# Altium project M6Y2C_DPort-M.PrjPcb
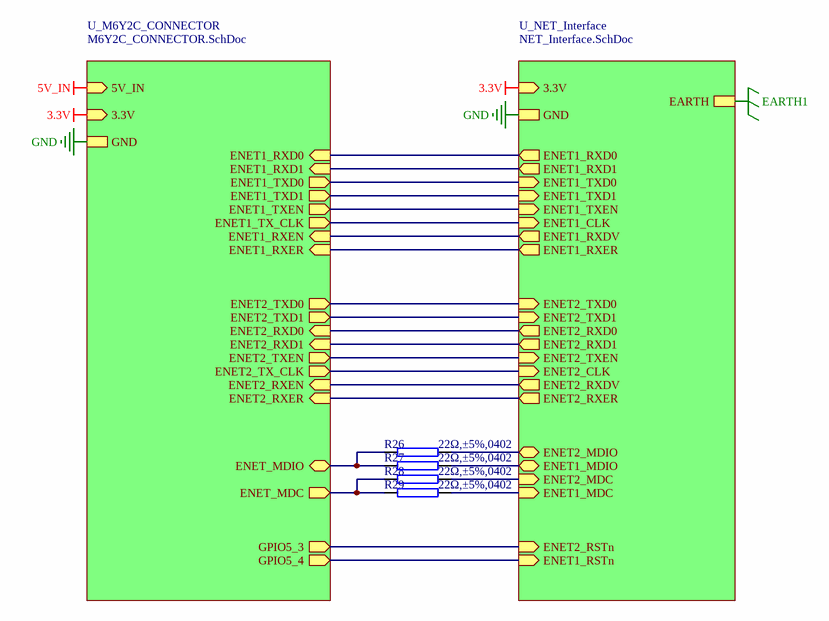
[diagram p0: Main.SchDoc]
3 sheets, 45 parts. Net scope: hierarchical (ports join the sheet entries above them; power ports are global).
Sheets:
  Main.SchDoc
    U_M6Y2C_CONNECTOR = M6Y2C_CONNECTOR.SchDoc
    U_NET_Interface = NET_Interface.SchDoc

## Sheet Main.SchDoc
size A4; CheckedBy: 工控机; Author: 工控机; SheetNumber: 01; PageSetup: Record=PageOptions¦CenterHorizontal=True¦CenterVertical=True¦PrintScale=1.00¦XCorrection=1.00¦YCorrection=1.00¦PrintKind=0¦BorderSize=5000000¦LeftOffset=0¦BottomOffset=0¦Orientation=2¦PaperLength=1000¦PaperWidth=1000¦Scale=100¦PaperSource=7¦PrintQuality=600¦MediaType=1¦DitherType=10¦PaperKind=A4¦PrintScaleMode=1; DesignDate: 2023/12/21; CheckDate: 2023/12/21; SheetName: Main; SheetVersion: Rev,A; SheetDescription: M6Y2C_DPort-M; ProductName: 集成式RJ45插座; ProductModel: DPort-M

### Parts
R26  22Ω,±5%,0402  [0402R]
R27  22Ω,±5%,0402  [0402R]
R28  22Ω,±5%,0402  [0402R]
R29  22Ω,±5%,0402  [0402R]

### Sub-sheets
U_M6Y2C_CONNECTOR = M6Y2C_CONNECTOR.SchDoc: ENET2_RXD1 (in), ENET2_RXD0 (in), ENET2_RXEN (in), ENET2_RXER (in), ENET_MDC (out), ENET2_TXD1 (out), ENET2_TXD0 (out), ENET2_TXEN (out), ENET2_TX_CLK (out), ENET_MDIO (bidir), ENET1_RXD1 (in), ENET1_RXD0 (in), ENET1_TXD1 (out), ENET1_TXD0 (out), ENET1_RXEN (in), ENET1_RXER (in), ENET1_TXEN (out), ENET1_TX_CLK (out), GND, 5V_IN (in), 3.3V (in), GPIO5_3 (out), GPIO5_4 (out)
U_NET_Interface = NET_Interface.SchDoc: GND, EARTH, ENET1_MDC (in), ENET1_RXDV (out), ENET1_TXEN (in), ENET1_MDIO (bidir), ENET1_RSTn (in), ENET1_TXD0 (in), ENET1_TXD1 (in), ENET1_RXD0 (out), ENET1_RXD1 (out), ENET1_CLK (in), ENET1_RXER (out), ENET2_MDC (in), ENET2_RXDV (out), ENET2_TXEN (in), ENET2_MDIO (bidir), ENET2_RSTn (in), ENET2_TXD0 (in), ENET2_TXD1 (in), ENET2_RXD0 (out), ENET2_RXD1 (out), ENET2_CLK (in), ENET2_RXER (out), 3.3V (in)

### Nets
3.3V: sheet U_M6Y2C_CONNECTOR/3.3V, sheet U_NET_Interface/3.3V
GND: sheet U_M6Y2C_CONNECTOR/GND, sheet U_NET_Interface/GND
ENET1_CLK: sheet U_M6Y2C_CONNECTOR/ENET1_TX_CLK, sheet U_NET_Interface/ENET1_CLK
ENET1_MDC: R29.2 ; sheet U_NET_Interface/ENET1_MDC
ENET1_MDIO: R27.2 ; sheet U_NET_Interface/ENET1_MDIO
ENET1_RSTn: sheet U_M6Y2C_CONNECTOR/GPIO5_4, sheet U_NET_Interface/ENET1_RSTn
ENET1_RXD0: sheet U_M6Y2C_CONNECTOR/ENET1_RXD0, sheet U_NET_Interface/ENET1_RXD0
ENET1_RXD1: sheet U_M6Y2C_CONNECTOR/ENET1_RXD1, sheet U_NET_Interface/ENET1_RXD1
ENET1_RXDV: sheet U_M6Y2C_CONNECTOR/ENET1_RXEN, sheet U_NET_Interface/ENET1_RXDV
ENET1_RXER: sheet U_M6Y2C_CONNECTOR/ENET1_RXER, sheet U_NET_Interface/ENET1_RXER
ENET1_TXD0: sheet U_M6Y2C_CONNECTOR/ENET1_TXD0, sheet U_NET_Interface/ENET1_TXD0
ENET1_TXD1: sheet U_M6Y2C_CONNECTOR/ENET1_TXD1, sheet U_NET_Interface/ENET1_TXD1
ENET1_TXEN: sheet U_M6Y2C_CONNECTOR/ENET1_TXEN, sheet U_NET_Interface/ENET1_TXEN
ENET2_CLK: sheet U_M6Y2C_CONNECTOR/ENET2_TX_CLK, sheet U_NET_Interface/ENET2_CLK
ENET2_MDC: R28.2 ; sheet U_NET_Interface/ENET2_MDC
ENET2_MDIO: R26.2 ; sheet U_NET_Interface/ENET2_MDIO
ENET2_RSTn: sheet U_M6Y2C_CONNECTOR/GPIO5_3, sheet U_NET_Interface/ENET2_RSTn
ENET2_RXD0: sheet U_M6Y2C_CONNECTOR/ENET2_RXD0, sheet U_NET_Interface/ENET2_RXD0
ENET2_RXD1: sheet U_M6Y2C_CONNECTOR/ENET2_RXD1, sheet U_NET_Interface/ENET2_RXD1
ENET2_RXDV: sheet U_M6Y2C_CONNECTOR/ENET2_RXEN, sheet U_NET_Interface/ENET2_RXDV
ENET2_RXER: sheet U_M6Y2C_CONNECTOR/ENET2_RXER, sheet U_NET_Interface/ENET2_RXER
ENET2_TXD0: sheet U_M6Y2C_CONNECTOR/ENET2_TXD0, sheet U_NET_Interface/ENET2_TXD0
ENET2_TXD1: sheet U_M6Y2C_CONNECTOR/ENET2_TXD1, sheet U_NET_Interface/ENET2_TXD1
ENET2_TXEN: sheet U_M6Y2C_CONNECTOR/ENET2_TXEN, sheet U_NET_Interface/ENET2_TXEN
ENET_MDC: R28.1 R29.1 ; sheet U_M6Y2C_CONNECTOR/ENET_MDC
ENET_MDIO: R26.1 R27.1 ; sheet U_M6Y2C_CONNECTOR/ENET_MDIO

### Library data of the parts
R26-R29 = 01.01.00014: RTT02220JTH,0402,RALEC,22Ω,±5%,1/16W,; 旧物料代码: 1.01.17.0023; 名称: 电阻; 封装: 0402; 贴片和直插: SMT; 环保状态: RoHS2.0+REACH; 器件优选方案: 通用物料; 生产单位: PCS

## Sheet M6Y2C_CONNECTOR.SchDoc
size A3; CheckedBy: 工控机; Author: 工控机; SheetNumber: 02; PageSetup: Record=PageOptions¦CenterHorizontal=True¦CenterVertical=True¦PrintScale=1.00¦XCorrection=1.00¦YCorrection=1.00¦PrintKind=0¦BorderSize=5000000¦LeftOffset=0¦BottomOffset=0¦Orientation=2¦PaperLength=1000¦PaperWidth=1000¦Scale=100¦PaperSource=7¦PrintQuality=600¦MediaType=1¦DitherType=10¦PaperKind=A4¦PrintScaleMode=1; DesignDate: 2023/12/21; CheckDate: 2023/12/21; SheetName: M6Y2C_CONNECTOER; SheetVersion: Rev.A; SheetDescription: M6Y2C_DPort-M; ProductName: 集成式RJ45插座; ProductModel: DPort-M
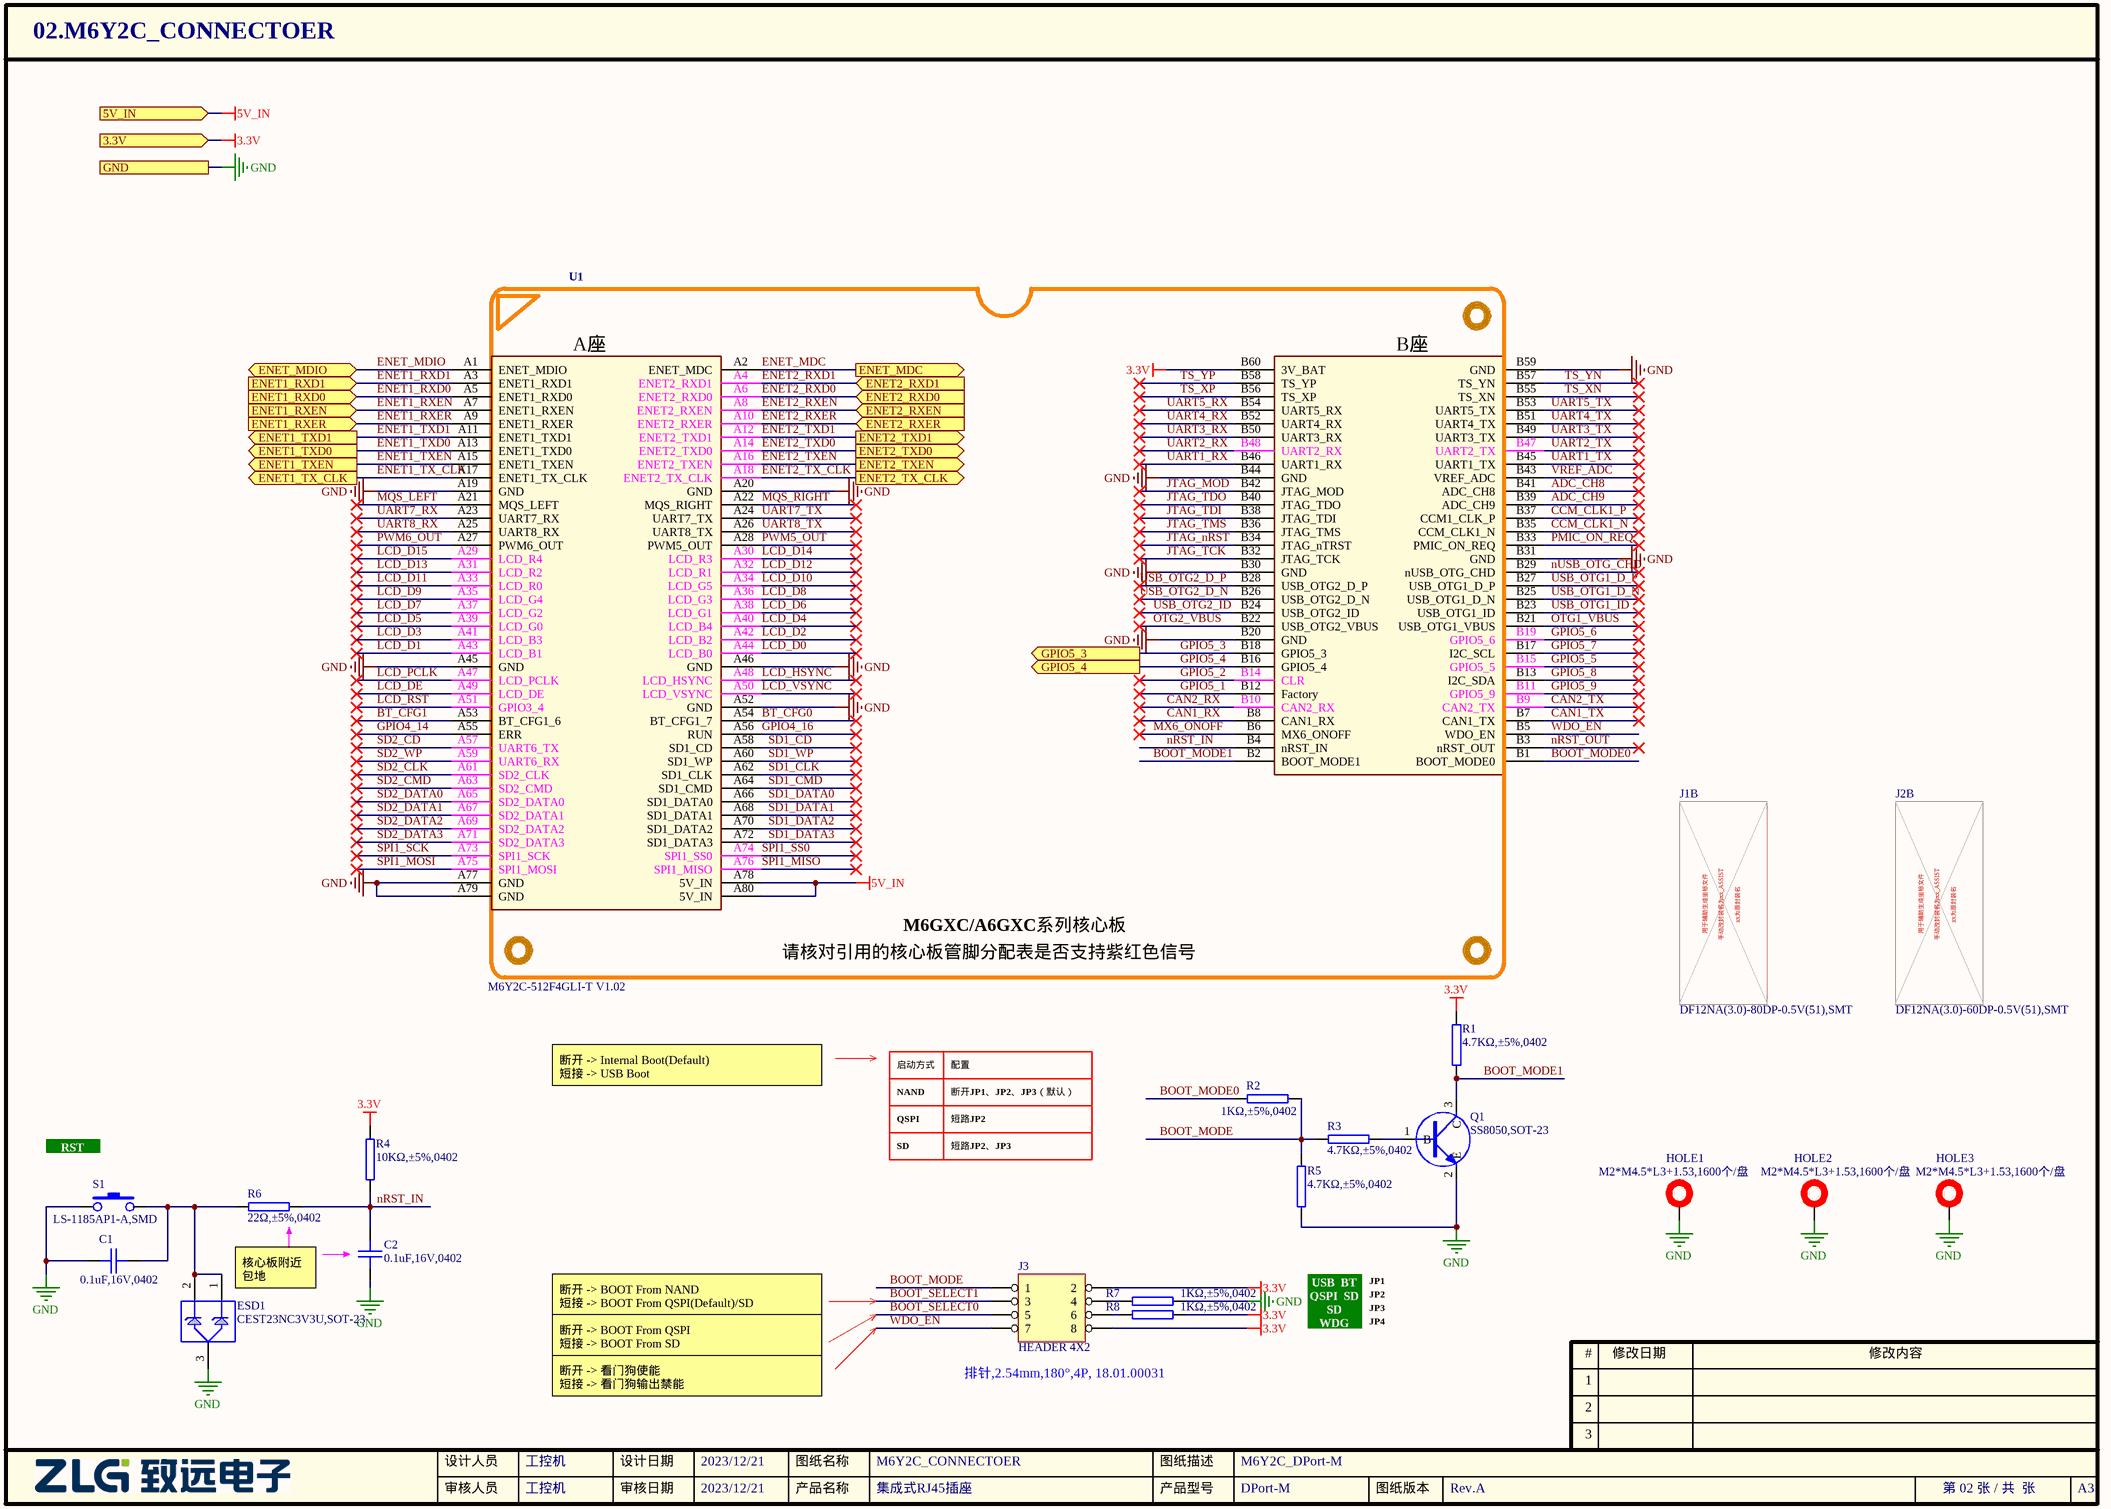
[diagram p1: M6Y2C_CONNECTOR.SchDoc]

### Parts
C1  0.1uF,16V,0402  [0402C]
C2  0.1uF,16V,0402  [0402C]
ESD1  CEST23NC3V3U,SOT-23  [SOT-23]
HOLE1  M2*M4.5*L3+1.53,1600个/盘  [Mou-Hole-300D450W310H-SMD]
HOLE2  M2*M4.5*L3+1.53,1600个/盘  [Mou-Hole-300D450W310H-SMD]
HOLE3  M2*M4.5*L3+1.53,1600个/盘  [Mou-Hole-300D450W310H-SMD]
J1  DF12NA(3.0)-80DP-0.5V(51),SMT  [SMTCON_DF12NA(3.0)-80DP-0.5V(51)]  (part B of 2)
J2  DF12NA(3.0)-60DP-0.5V(51),SMT  [SMTCON_DF12NA(3.0)-60DP-0.5V(51)]  (part B of 2)
J3  HEADER 4X2  [IDC-8-2.54]
Q1  SS8050,SOT-23  [SOT-23]
R1  4.7KΩ,±5%,0402  [0402R]
R2  1KΩ,±5%,0402  [0402R]
R3  4.7KΩ,±5%,0402  [0402R]
R4  10KΩ,±5%,0402  [0402R]
R5  4.7KΩ,±5%,0402  [0402R]
R6  22Ω,±5%,0402  [0402R]
R7  1KΩ,±5%,0402  [0402R]
R8  1KΩ,±5%,0402  [0402R]
S1  LS-1185AP1-A,SMD  [KEY-400X300X200P]
U1  M6Y2C-512F4GLI-T V1.02  [M6205/A6GXC]

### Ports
3.3V (in), 5V_IN (in), ENET1_RXD0 (in), ENET1_RXD1 (in), ENET1_RXEN (in), ENET1_RXER (in), ENET1_TX_CLK (out), ENET1_TXD0 (out), ENET1_TXD1 (out), ENET1_TXEN (out), ENET2_RXD0 (in), ENET2_RXD1 (in), ENET2_RXEN (in), ENET2_RXER (in), ENET2_TX_CLK (out), ENET2_TXD0 (out), ENET2_TXD1 (out), ENET2_TXEN (out), ENET_MDC (out), ENET_MDIO (bidir), GND, GPIO5_3 (out), GPIO5_4 (out)

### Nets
3.3V: J3.2 J3.8 R1.2 R4.2 R8.2 U1.B60(3V_BAT) ; port 3.3V
5V_IN: U1.A78(5V_IN) U1.A80(5V_IN) ; port 5V_IN
GND: C1.1 C2.2 ESD1.3 HOLE1.1 HOLE2.1 HOLE3.1 Q1.2(E) R5.1 R7.2 S1.1 U1.A19(GND) U1.A20(GND) U1.A45(GND) U1.A46(GND) U1.A52(GND) U1.A77(GND) U1.A79(GND) U1.B20(GND) U1.B30(GND) U1.B31(GND) U1.B44(GND) U1.B59(GND) ; port GND
ADC_CH8: U1.B41(ADC_CH8)
ADC_CH9: U1.B39(ADC_CH9)
BOOT_MODE: J3.1 R2.2 R3.1 R5.2
BOOT_MODE0: R2.1 U1.B1(BOOT_MODE0)
BOOT_MODE1: Q1.3(C) R1.1 U1.B2(BOOT_MODE1)
BOOT_SELECT0: J3.5
BOOT_SELECT1: J3.3
BT_CFG0: U1.A54(BT_CFG1_7)
BT_CFG1: U1.A53(BT_CFG1_6)
CAN1_RX: U1.B8(CAN1_RX)
CAN1_TX: U1.B7(CAN1_TX)
CAN2_RX: U1.B10(CAN2_RX)
CAN2_TX: U1.B9(CAN2_TX)
CCM_CLK1_N: U1.B35(CCM_CLK1_N)
CCM_CLK1_P: U1.B37(CCM1_CLK_P)
ENET1_RXD0: U1.A5(ENET1_RXD0) ; port ENET1_RXD0
ENET1_RXD1: U1.A3(ENET1_RXD1) ; port ENET1_RXD1
ENET1_RXEN: U1.A7(ENET1_RXEN) ; port ENET1_RXEN  [project net ENET1_RXDV]
ENET1_RXER: U1.A9(ENET1_RXER) ; port ENET1_RXER
ENET1_TX_CLK: U1.A17(ENET1_TX_CLK) ; port ENET1_TX_CLK  [project net ENET1_CLK]
ENET1_TXD0: U1.A13(ENET1_TXD0) ; port ENET1_TXD0
ENET1_TXD1: U1.A11(ENET1_TXD1) ; port ENET1_TXD1
ENET1_TXEN: U1.A15(ENET1_TXEN) ; port ENET1_TXEN
ENET2_RXD0: U1.A6(ENET2_RXD0) ; port ENET2_RXD0
ENET2_RXD1: U1.A4(ENET2_RXD1) ; port ENET2_RXD1
ENET2_RXEN: U1.A8(ENET2_RXEN) ; port ENET2_RXEN  [project net ENET2_RXDV]
ENET2_RXER: U1.A10(ENET2_RXER) ; port ENET2_RXER
ENET2_TX_CLK: U1.A18(ENET2_TX_CLK) ; port ENET2_TX_CLK  [project net ENET2_CLK]
ENET2_TXD0: U1.A14(ENET2_TXD0) ; port ENET2_TXD0
ENET2_TXD1: U1.A12(ENET2_TXD1) ; port ENET2_TXD1
ENET2_TXEN: U1.A16(ENET2_TXEN) ; port ENET2_TXEN
ENET_MDC: U1.A2(ENET_MDC) ; port ENET_MDC
ENET_MDIO: U1.A1(ENET_MDIO) ; port ENET_MDIO
GPIO4_14: U1.A55(ERR)
GPIO4_16: U1.A56(RUN)
GPIO5_1: U1.B12(Factory)
GPIO5_2: U1.B14(CLR)
GPIO5_3: U1.B18(GPIO5_3) ; port GPIO5_3  [project net ENET2_RSTn]
GPIO5_4: U1.B16(GPIO5_4) ; port GPIO5_4  [project net ENET1_RSTn]
GPIO5_5: U1.B15(GPIO5_5)
GPIO5_6: U1.B19(GPIO5_6)
GPIO5_7: U1.B17(I2C_SCL)
GPIO5_8: U1.B13(I2C_SDA)
GPIO5_9: U1.B11(GPIO5_9)
JTAG_MOD: U1.B42(JTAG_MOD)
JTAG_nRST: U1.B34(JTAG_nTRST)
JTAG_TCK: U1.B32(JTAG_TCK)
JTAG_TDI: U1.B38(JTAG_TDI)
JTAG_TDO: U1.B40(JTAG_TDO)
JTAG_TMS: U1.B36(JTAG_TMS)
LCD_D0: U1.A44(LCD_B0)
LCD_D1: U1.A43(LCD_B1)
LCD_D2: U1.A42(LCD_B2)
LCD_D3: U1.A41(LCD_B3)
LCD_D4: U1.A40(LCD_B4)
LCD_D5: U1.A39(LCD_G0)
LCD_D6: U1.A38(LCD_G1)
LCD_D7: U1.A37(LCD_G2)
LCD_D8: U1.A36(LCD_G3)
LCD_D9: U1.A35(LCD_G4)
LCD_D10: U1.A34(LCD_G5)
LCD_D11: U1.A33(LCD_R0)
LCD_D12: U1.A32(LCD_R1)
LCD_D13: U1.A31(LCD_R2)
LCD_D14: U1.A30(LCD_R3)
LCD_D15: U1.A29(LCD_R4)
LCD_DE: U1.A49(LCD_DE)
LCD_HSYNC: U1.A48(LCD_HSYNC)
LCD_PCLK: U1.A47(LCD_PCLK)
LCD_RST: U1.A51(GPIO3_4)
LCD_VSYNC: U1.A50(LCD_VSYNC)
MQS_LEFT: U1.A21(MQS_LEFT)
MQS_RIGHT: U1.A22(MQS_RIGHT)
MX6_ONOFF: U1.B6(MX6_ONOFF)
nRST_IN: C2.1 R4.1 R6.2 U1.B4(nRST_IN)
nRST_OUT: U1.B3(nRST_OUT)
nUSB_OTG_CHD: U1.B29(nUSB_OTG_CHD)
OTG1_VBUS: U1.B21(USB_OTG1_VBUS)
OTG2_VBUS: U1.B22(USB_OTG2_VBUS)
PMIC_ON_REQ: U1.B33(PMIC_ON_REQ)
PWM5_OUT: U1.A28(PWM5_OUT)
PWM6_OUT: U1.A27(PWM6_OUT)
SD1_CD: U1.A58(SD1_CD)
SD1_CLK: U1.A62(SD1_CLK)
SD1_CMD: U1.A64(SD1_CMD)
SD1_DATA0: U1.A66(SD1_DATA0)
SD1_DATA1: U1.A68(SD1_DATA1)
SD1_DATA2: U1.A70(SD1_DATA2)
SD1_DATA3: U1.A72(SD1_DATA3)
SD1_WP: U1.A60(SD1_WP)
SD2_CD: U1.A57(UART6_TX)
SD2_CLK: U1.A61(SD2_CLK)
SD2_CMD: U1.A63(SD2_CMD)
SD2_DATA0: U1.A65(SD2_DATA0)
SD2_DATA1: U1.A67(SD2_DATA1)
SD2_DATA2: U1.A69(SD2_DATA2)
SD2_DATA3: U1.A71(SD2_DATA3)
SD2_WP: U1.A59(UART6_RX)
SPI1_MISO: U1.A76(SPI1_MISO)
SPI1_MOSI: U1.A75(SPI1_MOSI)
SPI1_SCK: U1.A73(SPI1_SCK)
SPI1_SS0: U1.A74(SPI1_SS0)
TS_XN: U1.B55(TS_XN)
TS_XP: U1.B56(TS_XP)
TS_YN: U1.B57(TS_YN)
TS_YP: U1.B58(TS_YP)
UART1_RX: U1.B46(UART1_RX)
UART1_TX: U1.B45(UART1_TX)
UART2_RX: U1.B48(UART2_RX)
UART2_TX: U1.B47(UART2_TX)
UART3_RX: U1.B50(UART3_RX)
UART3_TX: U1.B49(UART3_TX)
UART4_RX: U1.B52(UART4_RX)
UART4_TX: U1.B51(UART4_TX)
UART5_RX: U1.B54(UART5_RX)
UART5_TX: U1.B53(UART5_TX)
UART7_RX: U1.A23(UART7_RX)
UART7_TX: U1.A24(UART7_TX)
UART8_RX: U1.A25(UART8_RX)
UART8_TX: U1.A26(UART8_TX)
USB_OTG1_D_N: U1.B25(USB_OTG1_D_N)
USB_OTG1_D_P: U1.B27(USB_OTG1_D_P)
USB_OTG1_ID: U1.B23(USB_OTG1_ID)
USB_OTG2_D_N: U1.B26(USB_OTG2_D_N)
USB_OTG2_D_P: U1.B28(USB_OTG2_D_P)
USB_OTG2_ID: U1.B24(USB_OTG2_ID)
VREF_ADC: U1.B43(VREF_ADC)
WDO_EN: J3.7 U1.B5(WDO_EN)
NetC1_2: C1.2 ESD1.1 ESD1.2 R6.1 S1.2
NetJ3_4: J3.4 R7.1
NetJ3_6: J3.6 R8.1
NetQ1_1: Q1.1(B) R3.2

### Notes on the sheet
- 断开 -> Internal Boot(Default)
  短接 -> USB Boot
- 启动方式
- NAND
- QSPI
- 断开JP1、JP2、JP3（默认）
- 短路JP2
- 配置
- RST
- SD
- 短路JP2、JP3
- (near ESD1) 核心板附近 包地
- 断开 -> BOOT From NAND
  短接 -> BOOT From QSPI(Default)/SD
- USB_BT
- QSPI_SD
- WDG
- JP1
- JP2
- JP3
- JP4
- 断开 -> 看门狗使能
  短接 -> 看门狗输出禁能
- 断开 -> BOOT From QSPI
  短接 -> BOOT From SD
- 排针,2.54mm,180°,4P, 18.01.00031

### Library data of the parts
C1 C2 = 02.01.00513: CC0402KRX7R7BB104,0402,YAGEO,0.1uF,X7R,±10%,16V,; 名称: 电容; 封装: 0402; 贴片和直插: SMT; 环保状态: RoHS2.0; PCB备注: 211228yyj; 器件优选方案: 通用物料; 生产单位: PCS
ESD1 = 09.04.00444: CEST23NC3V3U,SOT-23,CREATEK; 名称: ESD静电保护器件; 贴片和直插: SMT; 环保状态: RoHS2.0; 器件优选方案: 通用物料; 生产单位: PCS; PCB备注: 220609lmd
HOLE1-HOLE3 = 27.41.00039: M2*M4.5*L3+1.53,1600个/盘,雄和远景; 名称: 螺柱; 贴片和直插: SMT; PCB备注: 160330lmd; 器件优选方案: 通用物料; 旧物料代码: 1.15.03.0047
J1 = 18.04.00097: DF12NA(3.0)-80DP-0.5V(51),SMT,HRS; 名称: 板对板连接器; 环保状态: RoHS2.0; PCB备注: 210805ZW; 器件优选方案: 通用物料; 生产单位: PCS
J2 = 18.04.00099: DF12NA(3.0)-60DP-0.5V(51),SMT,HRS; 名称: 板对板连接器; 环保状态: RoHS2.0; PCB备注: 210805ZW; 器件优选方案: 通用物料; 生产单位: PCS
Q1 = 05.01.00095: SS8050,SOT-23,JCET,NPN,; 旧物料代码: 1.04.09.0001; 名称: 双极结型晶体管(三极管); 贴片和直插: SMT; 环保状态: RoHS2.0+REACH; 器件优选方案: 通用物料; 生产单位: PCS
R1 R3 R5 = 01.01.00003: RTT02472JTH,0402,RALEC,4.7KΩ,±5%,1/16W,; 旧物料代码: 1.01.17.0019; 名称: 电阻; 封装: 0402; 贴片和直插: SMT; 环保状态: RoHS2.0+REACH; 器件优选方案: 通用物料; 生产单位: PCS
R2 = 01.01.00007: RTT02102JTH,0402,RALEC,1KΩ,±5%,1/16W,; 旧物料代码: 1.01.17.0022; 名称: 电阻; 封装: 0402; 贴片和直插: SMT; 环保状态: RoHS2.0+REACH; 器件优选方案: 通用物料; 生产单位: PCS
R4 = 01.01.00001: RTT02103JTH,0402,RALEC,10KΩ,±5%,1/16W; 旧物料代码: 1.01.17.0006; 名称: 电阻; 封装: 0402; 贴片和直插: SMT; 环保状态: RoHS2.0; 器件优选方案: 通用物料; 生产单位: PCS
R6 = 01.01.00014: as R26 on sheet Main
R7 R8 = 01.01.00007: RTT02102JTH,0402,RALEC,1KΩ,±5%,1/16W,; 旧物料代码: 1.01.17.0022; 名称: 电阻; 封装: 0402; 贴片和直插: SMT; 器件优选方案: 通用物料
S1 = 17.01.00009: LS-1185AP1-A,SMD,CKC,4*3*2mm,; 旧物料代码: 1.09.01.0017; 名称: 轻触开关; 封装: SMT; 环保状态: RoHS2.0; PCB备注: 161024 HCJ; 器件优选方案: 通用物料; 生产单位: PCS
U1 = 80.08.90523: 名称: 核心板; PCB备注: 221027hcj; 厂商: ZHIYUAN; 环保状态: RoHS2.0; 生产单位: PCS

## Sheet NET_Interface.SchDoc
size A4; CheckedBy: 工控机; Author: 工控机; SheetNumber: 2; SheetTotal: 2; PageSetup: Record=PageOptions¦CenterHorizontal=True¦CenterVertical=True¦PrintScale=1.00¦XCorrection=1.00¦YCorrection=1.00¦PrintKind=0¦BorderSize=5000000¦LeftOffset=0¦BottomOffset=0¦Orientation=2¦PaperLength=1000¦PaperWidth=1000¦Scale=100¦PaperSource=7¦PrintQuality=600¦MediaType=1¦DitherType=10¦PaperKind=A4¦PrintScaleMode=1; DesignDate: 2023/12/21; CheckDate: 2023/12/21; SheetName: NET_Interface; SheetVersion: Rev.A; SheetDescription: 集成PHY和网络变压器的双口RJ45; ProductName: RJ45插座; ProductModel: DPort-M
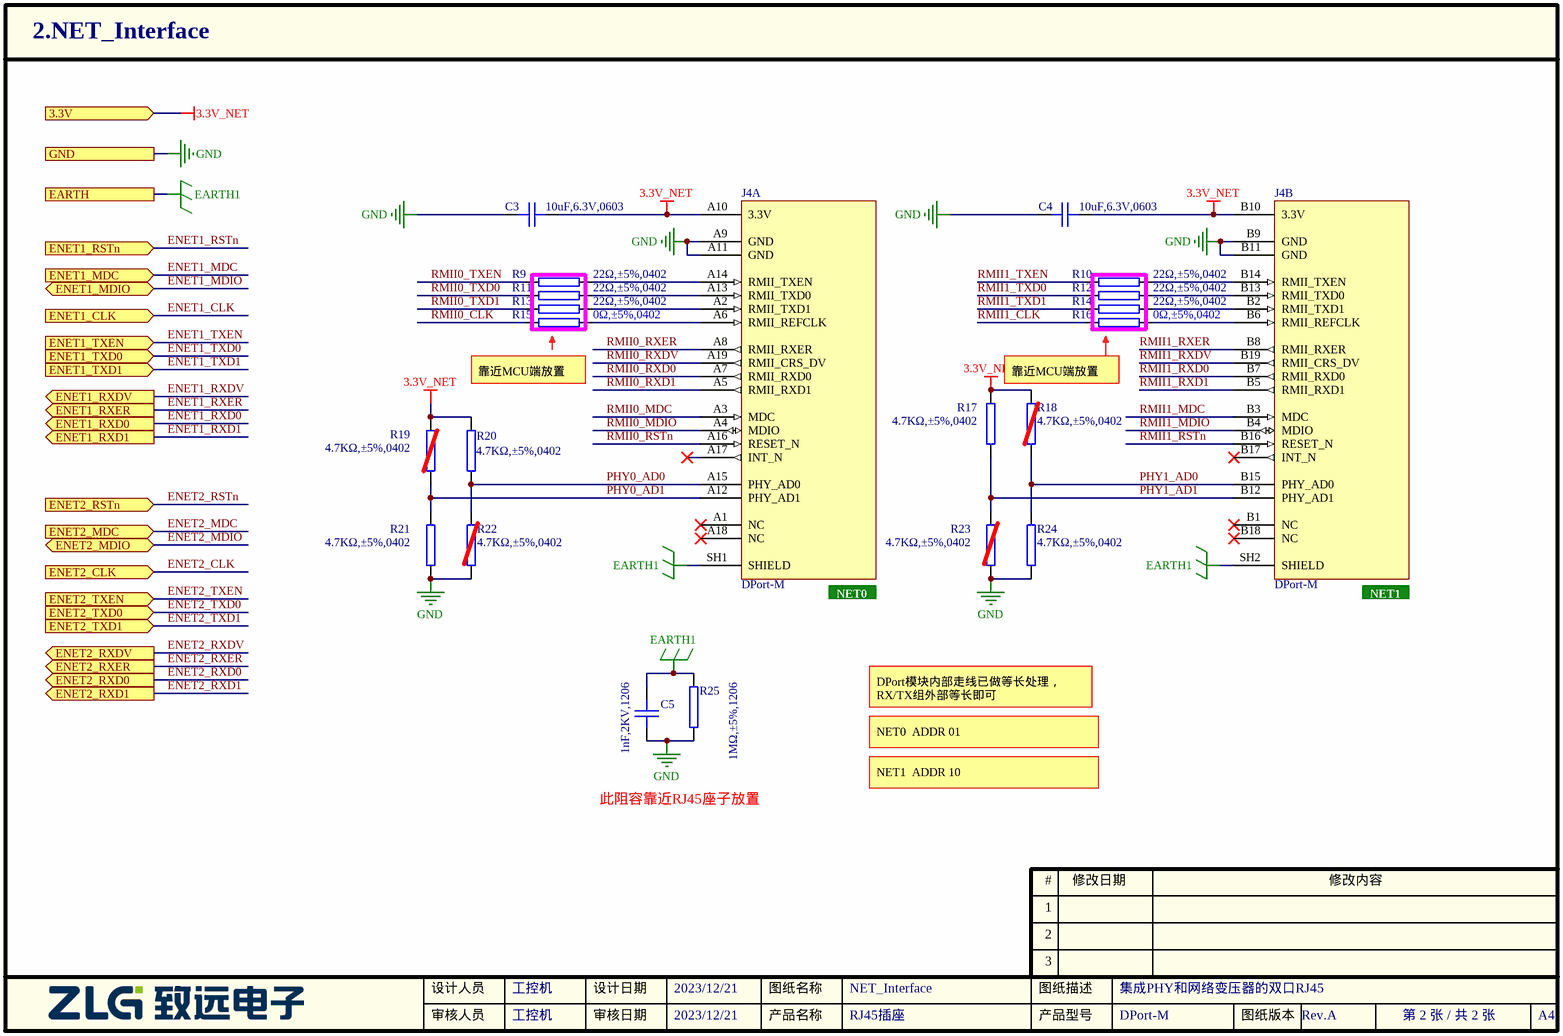
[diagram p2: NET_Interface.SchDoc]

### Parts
C3  10uF,6.3V,0603  [0603C]
C4  10uF,6.3V,0603  [0603C]
C5  1nF,2KV,1206  [1206C]
J4  DPort-M  [DPort-M]  (parts A,B of 2)
R9  22Ω,±5%,0402  [0402R]
R10  22Ω,±5%,0402  [0402R]
R11  22Ω,±5%,0402  [0402R]
R12  22Ω,±5%,0402  [0402R]
R13  22Ω,±5%,0402  [0402R]
R14  22Ω,±5%,0402  [0402R]
R15  0Ω,±5%,0402  [0402R]
R16  0Ω,±5%,0402  [0402R]
R17  4.7KΩ,±5%,0402  [0402R]
R18  4.7KΩ,±5%,0402  [0402R]
R19  4.7KΩ,±5%,0402  [0402R]
R20  4.7KΩ,±5%,0402  [0402R]
R21  4.7KΩ,±5%,0402  [0402R]
R22  4.7KΩ,±5%,0402  [0402R]
R23  4.7KΩ,±5%,0402  [0402R]
R24  4.7KΩ,±5%,0402  [0402R]
R25  1MΩ,±5%,1206  [1206R]

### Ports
3.3V (in), EARTH, ENET1_CLK (in), ENET1_MDC (in), ENET1_MDIO (bidir), ENET1_RSTn (in), ENET1_RXD0 (out), ENET1_RXD1 (out), ENET1_RXDV (out), ENET1_RXER (out), ENET1_TXD0 (in), ENET1_TXD1 (in), ENET1_TXEN (in), ENET2_CLK (in), ENET2_MDC (in), ENET2_MDIO (bidir), ENET2_RSTn (in), ENET2_RXD0 (out), ENET2_RXD1 (out), ENET2_RXDV (out), ENET2_RXER (out), ENET2_TXD0 (in), ENET2_TXD1 (in), ENET2_TXEN (in), GND

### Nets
3.3V_NET: C3.2 C4.2 J4.A10(3.3V) J4.B10(3.3V) R17.2 R18.2 R19.2 R20.2 ; port 3.3V  [project net 3.3V]
EARTH1: C5.2 J4.SH1(SHIELD) J4.SH2(SHIELD) R25.2 ; port EARTH
GND: C3.1 C4.1 C5.1 J4.A9(GND) J4.A11(GND) J4.B9(GND) J4.B11(GND) R21.1 R22.1 R23.1 R24.1 R25.1 ; port GND
PHY0_AD0: J4.A15(PHY_AD0) R20.1 R22.2
PHY0_AD1: J4.A12(PHY_AD1) R19.1 R21.2
PHY1_AD0: J4.B15(PHY_AD0) R18.1 R24.2
PHY1_AD1: J4.B12(PHY_AD1) R17.1 R23.2
RMII0_CLK: R15.1
RMII0_MDC: J4.A3(MDC)
RMII0_MDIO: J4.A4(MDIO)
RMII0_RSTn: J4.A16(RESET_N)
RMII0_RXD0: J4.A7(RMII_RXD0)
RMII0_RXD1: J4.A5(RMII_RXD1)
RMII0_RXDV: J4.A19(RMII_CRS_DV)
RMII0_RXER: J4.A8(RMII_RXER)
RMII0_TXD0: R11.1
RMII0_TXD1: R13.1
RMII0_TXEN: R9.1
RMII1_CLK: R16.1
RMII1_MDC: J4.B3(MDC)
RMII1_MDIO: J4.B4(MDIO)
RMII1_RSTn: J4.B16(RESET_N)
RMII1_RXD0: J4.B7(RMII_RXD0)
RMII1_RXD1: J4.B5(RMII_RXD1)
RMII1_RXDV: J4.B19(RMII_CRS_DV)
RMII1_RXER: J4.B8(RMII_RXER)
RMII1_TXD0: R12.1
RMII1_TXD1: R14.1
RMII1_TXEN: R10.1
NetJ4_A2: J4.A2(RMII_TXD1) R13.2
NetJ4_A6: J4.A6(RMII_REFCLK) R15.2
NetJ4_A13: J4.A13(RMII_TXD0) R11.2
NetJ4_A14: J4.A14(RMII_TXEN) R9.2
NetJ4_B2: J4.B2(RMII_TXD1) R14.2
NetJ4_B6: J4.B6(RMII_REFCLK) R16.2
NetJ4_B13: J4.B13(RMII_TXD0) R12.2
NetJ4_B14: J4.B14(RMII_TXEN) R10.2

Not connected (* = marked no-connect by the designer): J4 A1(NC)* A17(INT_N)* A18(NC)* B1(NC)* B17(INT_N)* B18(NC)*

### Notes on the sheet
- 靠近MCU端放置
- NET0
- NET1
- DPort模块内部走线已做等长处理，
  RX/TX组外部等长即可
- NET0  ADDR 01
- NET1  ADDR 10
- 此阻容靠近RJ45座子放置

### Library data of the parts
C3 C4 = 02.01.00155: GRM188R60J106M****,0603,MURATA,10uF,X5R,±20%,6.3V,; 旧物料代码: 1.02.01.0065; 名称: 电容; 封装: 0603; 贴片和直插: SMT; 环保状态: RoHS2.0+REACH; 器件优选方案: 通用物料; 生产单位: PCS
C5 = 02.01.00212: CC1206KKX7RDBB102,1206,YAGEO,1nF,X7R,±10%,2KV,; 名称: 电容; 封装: 1206; 贴片和直插: SMT; 旧物料代码: 1.02.03.0003; 器件优选方案: 不推荐使用
R9-R14 = 01.01.00014: as R26 on sheet Main
R15 R16 = 01.01.00004: RTT02000JTH,0402,RALEC,0Ω,±5%,1/16W,; 旧物料代码: 1.01.17.0004; 名称: 电阻; 封装: 0402; 贴片和直插: SMT; 器件优选方案: 通用物料; 现有库存: 428204
R17-R24 = 01.01.00003: RTT02472JTH,0402,RALEC,4.7KΩ,±5%,1/16W,; 名称: 电阻; 封装: 0402; 贴片和直插: SMT; 旧物料代码: 1.01.17.0019; 环保状态: RoHS2.0+REACH; 器件优选方案: 通用物料; 生产单位: PCS
R25 = 01.01.00041: RTT06105JTP,1206,RALEC,1MΩ,±5%,1/4W,; 名称: 电阻; 封装: 1206; 贴片和直插: SMT; 旧物料代码: 1.01.03.0019; 器件优选方案: 通用物料

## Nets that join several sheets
3.3V: M6Y2C_CONNECTOR (6 pins), NET_Interface (8 pins)
GND: M6Y2C_CONNECTOR (22 pins), NET_Interface (12 pins)
ENET_MDC: Main (R28.1 R29.1), M6Y2C_CONNECTOR (U1.A2)
ENET_MDIO: Main (R26.1 R27.1), M6Y2C_CONNECTOR (U1.A1)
